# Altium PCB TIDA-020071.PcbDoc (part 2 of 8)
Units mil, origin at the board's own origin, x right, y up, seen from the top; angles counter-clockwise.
Board outline 5750 x 4050 mil, 6 copper layers (Top Layer, GND PLANE-1, SIGNAL LAYER, SIGNAL/POWER LAYER, GND PLANE-2, Bottom Layer), stack 59.616 mil thick; 776 components, 498 nets, 2205 pads, 871 vias.
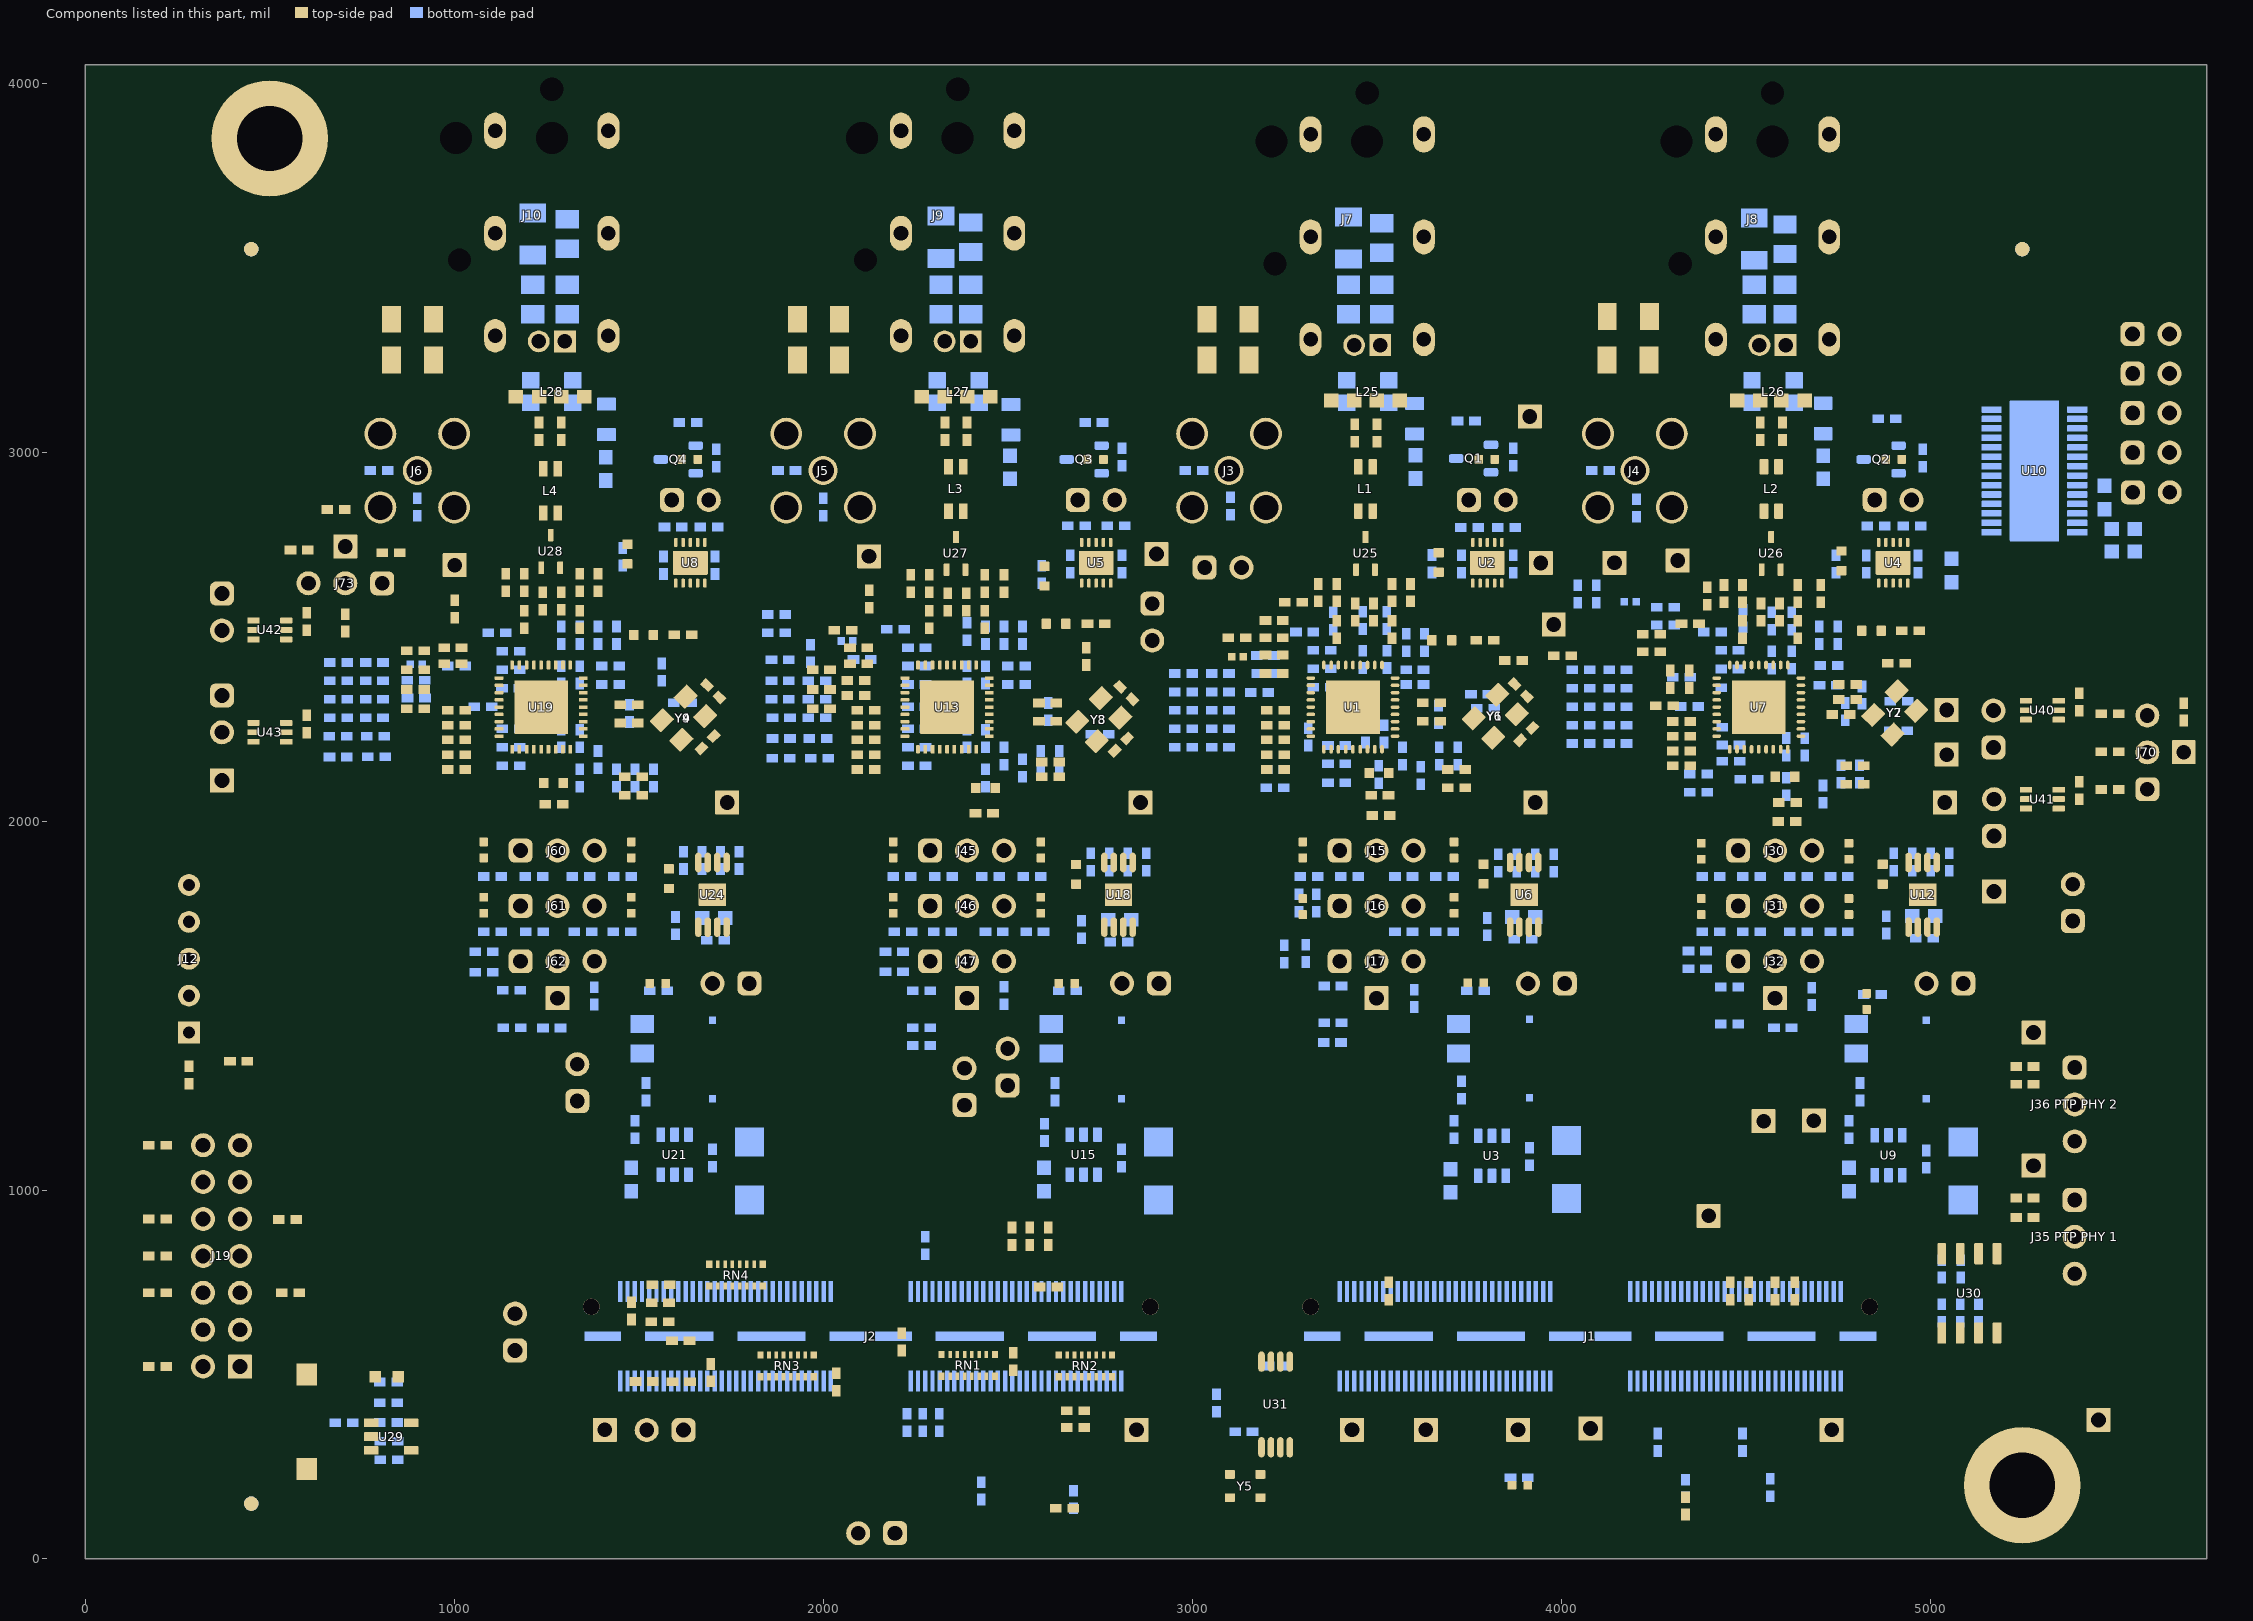
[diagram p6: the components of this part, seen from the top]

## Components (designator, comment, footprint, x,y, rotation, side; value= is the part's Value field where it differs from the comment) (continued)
R128 "CRCW04022K49FKED" 0402 2463.62,1700 r0 bottom value=2.49k
R129 "CRCW04022K20JNED" 0402 2192.68,1645.59 r0 bottom value=2.2k
R129-1 "CRCW040210K0FKED" 0402 2266.38,1540 r0 bottom value=10.0k
R129-2 "CRCW04022K20JNED" 0402 2490,1527.05 r270 bottom value=2.2k
R130 "ERJ-2GE0R00X" 0402 2750.8,2235.61 r0 bottom value=0
R131 "CRCW04022K20JNED" 0402 2733.62,3080 r0 bottom value=2.2k
R132 "CRCW04022K20JNED" 0402 2810,2986.38 r270 bottom value=2.2k
R133 "CRCW04022K20JNED" 0402 2662.11,1540 r0 bottom value=2.2k
R134 "ERJ-2GE0R00X" 0402 1562.35,2403.4 r270 bottom value=0
R135 "CRCW04022K49FKED" 0402 1886.38,2224 r180 bottom value=2.49k
R136 "CRCW04022K49FKED" 0402 1986.38,2224 r180 bottom value=2.49k
R137 "CRCW04022K49FKED" 0402 1886.38,2280 r180 bottom value=2.49k
R138 "CRCW04022K49FKED" 0402 1983.62,2280 r180 bottom value=2.49k
R139 "CRCW04022K49FKED" 0402 1883.62,2330 r180 bottom value=2.49k
R140 "CRCW04022K49FKED" 0402 1983.62,2330 r180 bottom value=2.49k
R141 "RC0402FR-074K7L" 0402 1883.62,2380 r180 bottom value=4.70k
R142 "CRCW04022K49FKED" 0402 1983.62,2380 r180 bottom value=2.49k
R143 "CRCW04022K49FKED" 0402 1883.6,2437.5 r180 bottom value=2.49k
R144 "CRCW04022K49FKED" 0402 1965.79,2454.41 r270 bottom value=2.49k
R145 "CRCW04020000Z0EDHP" 0402 2540,2503.62 r90 bottom value=0
R146 "CRCW04020000Z0EDHP" 0402 2196.38,2520 r180 bottom value=0
R147 "CRCW04020000Z0EDHP" 0402 2390,2513.62 r90 bottom value=0
R148 "CRCW04020000Z0EDHP" 0402 2253.62,2150 r0 bottom value=0
R149 "CRCW04020000Z0EDHP" 0402 2440,2116.38 r270 bottom value=0
R150 "CRCW04020000Z0EDHP" 0402 2700,1706.38 r270 bottom value=0
R151 "ERJ-2GE0R00X" 0402 1618.73,2320.66 r0 bottom value=0
R152 "CRCW04020000Z0EDHP" 0402 2266.38,1440 r0 bottom value=0
R153 "CRCW04020000Z0EDHP" 0402 2616.38,2160 r180 top value=0
R154 "CRCW04022K20JNED" 0402 2616.38,2120 r0 top value=2.2k
R155 "CRCW04022K20JNED" 0402 2640,2166.38 r270 bottom value=2.2k
R156 "CRCW04020000Z0EDHP" 0402 2590,2166.38 r270 bottom value=0
R157 "CRCW04020000Z0EDHP" 0402 2540,2143.62 r270 bottom value=0
R158 "CRCW04020000Z0EDHP" 0402 2116.38,2140 r180 top value=0
R159 "CRCW04020000Z0EDHP" 0402 2096.38,2470 r180 top value=0
R160 "CRCW04020000Z0EDHP" 0402 2116.38,2180 r180 top value=0
R161 "CRCW04020000Z0EDHP" 0402 2116.38,2220 r180 top value=0
R162 "CRCW04020000Z0EDHP" 0402 2116.38,2260 r180 top value=0
R163 "CRCW04020000Z0EDHP" 0402 2116.38,2300 r180 top value=0
R164 "ERJ-2GE0R00X" 0402 2000,2851.38 r90 bottom value=0
R165 "CRCW0402100RFKED" 0402 2608.46,2320.11 r180 top value=100
R166 "CRCW04021K00FKED" 0402 2608.46,2270.11 r180 top value=1.00k
R167 "CRCW04021K00FKED" 0402 1873.62,2560 r0 bottom value=1.00k
R168 "RMCF0805ZT0R00" FP-RMCF0805ZT0R00_0805-MFG 3603.12,3090.47 r270 bottom
R169 "CRCW040210K0FKED" 0402 2428.58,184.86 r90 bottom value=10.0k
R170 "CRCW040233K2FKED" 0402 1520,1266.38 r90 bottom value=33.2k
R171 "CRCW040210K0FKED" 0402 1490,1163.62 r270 bottom value=10.0k
R172 "CRCW04021K13FKED" 0402 1593.48,2796.89 r180 bottom value=1.13k
R173 "CRCW04024K53FKED" 0402 1690.73,2796.89 r180 bottom value=4.53k
R174 "CRCW04022K49FKED" 0402 1216.38,1850 r180 bottom value=2.49k
R175 "CRCW04022K20JNED" 0402 1103.62,1850 r0 bottom value=2.2k
R176 "CRCW04022K20JNED" 0402 1456.38,1850 r180 bottom value=2.2k
R177 "CRCW04022K49FKED" 0402 1343.62,1850 r0 bottom value=2.49k
R178 "CRCW04022K49FKED" 0402 1217.75,1700 r180 bottom value=2.49k
R179 "CRCW04022K20JNED" 0402 1103.62,1700 r0 bottom value=2.2k
R180 "CRCW04022K20JNED" 0402 1455,1700 r180 bottom value=2.2k
R181 "CRCW04022K49FKED" 0402 1349.21,1700 r0 bottom value=2.49k
R182 "CRCW04022K20JNED" 0402 1080.69,1645.59 r0 bottom value=2.2k
R182-1 "CRCW040210K0FKED" 0402 1155.24,1541.59 r0 bottom value=10.0k
R182-2 "CRCW04022K20JNED" 0402 1380,1526.38 r270 bottom value=2.2k
R183 "RMCF0805ZT0R00" FP-RMCF0805ZT0R00_0805-MFG 4710.44,3091.06 r270 bottom
R184 "CRCW04022K20JNED" 0402 1633.62,3080 r0 bottom value=2.2k
R185 "CRCW04022K20JNED" 0402 1710,2983.62 r270 bottom value=2.2k
R186 "CRCW04022K20JNED" 0402 1553.62,1540 r0 bottom value=2.2k
R187 "RMCF0805ZT0R00" FP-RMCF0805ZT0R00_0805-MFG 2508.66,3087.65 r270 bottom
R188 "CRCW04022K49FKED" 0402 685,2230 r180 bottom value=2.49k
R189 "CRCW04022K49FKED" 0402 786.38,2230 r180 bottom value=2.49k
R190 "CRCW04022K49FKED" 0402 686.38,2280 r180 bottom value=2.49k
R191 "CRCW04022K49FKED" 0402 783.62,2280 r180 bottom value=2.49k
R192 "CRCW04022K49FKED" 0402 686.38,2330 r180 bottom value=2.49k
R193 "CRCW04022K49FKED" 0402 783.62,2330 r180 bottom value=2.49k
R194 "CRCW04022K49FKED" 0402 686.38,2380 r180 bottom value=2.49k
R195 "CRCW04022K49FKED" 0402 783.62,2380 r180 bottom value=2.49k
R196 "RC0402FR-0710KL" 0402 686.38,2430 r180 bottom value=10.0k
R197 "CRCW04022K49FKED" 0402 783.62,2430 r180 bottom value=2.49k
R198 "CRCW04020000Z0EDHP" 0402 1440,2503.62 r90 bottom value=0
R199 "CRCW04020000Z0EDHP" 0402 1116.38,2510 r180 bottom value=0
R200 "CRCW04020000Z0EDHP" 0402 1340,2503.62 r90 bottom value=0
R201 "CRCW04020000Z0EDHP" 0402 1153.62,2150 r0 bottom value=0
R202 "CRCW04020000Z0EDHP" 0402 1340,2116.38 r270 bottom value=0
R203 "CRCW04020000Z0EDHP" 0402 1600,1716.38 r270 bottom value=0
R204 "RMCF0805ZT0R00" FP-RMCF0805ZT0R00_0805-MFG 1412.78,3088.69 r270 bottom
R205 "CRCW04020000Z0EDHP" 0402 1156.38,1440 r0 bottom value=0
R206 "CRCW04020000Z0EDHP" 0402 1486.38,2120 r180 top value=0
R207 "CRCW04022K20JNED" 0402 1486.38,2070 r0 top value=2.2k
R208 "CRCW04022K20JNED" 0402 1540,2116.38 r270 bottom value=2.2k
R209 "CRCW04020000Z0EDHP" 0402 1490,2116.38 r270 bottom value=0
R210 "CRCW04020000Z0EDHP" 0402 1440,2116.38 r90 bottom value=0
R211 "CRCW04020000Z0EDHP" 0402 1006.38,2140 r180 top value=0
R212 "CRCW04020000Z0EDHP" 0402 996.38,2470 r180 top value=0
R213 "CRCW04020000Z0EDHP" 0402 1006.38,2180 r180 top value=0
R214 "CRCW04020000Z0EDHP" 0402 1006.38,2220 r180 top value=0
R215 "CRCW04020000Z0EDHP" 0402 1006.38,2260 r180 top value=0
R216 "CRCW04020000Z0EDHP" 0402 1006.38,2300 r180 top value=0
R217 "ERJ-2GE0R00X" 0402 900,2851.38 r90 bottom value=0
R218 "CRCW0402100RFKED" 0402 1473.82,2315.55 r180 top value=100
R219 "CRCW04021K00FKED" 0402 1473.82,2265.55 r180 top value=1.00k
R220 "CRCW060310K0FKEA" 0603 5523.83,2730.7 r180 bottom value=10.0k
R221 "CRCW04020000Z0EDHP" 0402 3441.73,2566.14 r270 top value=0
R222 "CRCW04020000Z0EDHP" 0402 3491.73,2566.14 r270 top value=0
R223 "CRCW040226R7FKED" 0402 3391.73,2618.9 r270 top value=26.7
R224 "CRCW040226R7FKED" 0402 3541.73,2618.9 r90 top value=26.7
R225 "ERJ-P06F1001V" 0805_HV 3514.26,3413.28 r270 bottom value=1.00k
R226 "ERJ-P06F1001V" 0805_HV 3423.94,3413.28 r270 bottom value=1.00k
R227 "CRCW0805100KFKEA" 0805_HV 3514.26,3580.42 r270 bottom value=100k
R228 "CRCW12061M00JNEA" 1206 3097.09,3360 r180 top value=1.0Meg
R229 "CRCW060310K0FKEA" 0603 5523.83,2791.5 r180 bottom value=10.0k
R230 "CRCW06033K30JNEA" 0603 5472.83,2876.76 r90 bottom value=3.3k
R232 "CRCW04020000Z0EDHP" 0402 4541.73,2566.14 r270 top value=0
R233 "CRCW04020000Z0EDHP" 0402 4591.73,2566.14 r270 top value=0
R234 "CRCW040226R7FKED" 0402 4491.73,2616.14 r270 top value=26.7
R235 "CRCW040226R7FKED" 0402 4641.73,2616.14 r90 top value=26.7
R236 "ERJ-P06F1001V" 0805_HV 4607.16,3413.22 r270 bottom value=1.00k
R237 "ERJ-P06F1001V" 0805_HV 4523.48,3413.31 r270 bottom value=1.00k
R238 "CRCW0805100KFKEA" 0805_HV 4607.16,3576.85 r270 bottom value=100k
R239 "CRCW12061M00JNEA" 1206 4182.06,3367.29 r180 top value=1.0Meg
R243 "CRCW04020000Z0EDHP" 0402 2337.64,2593.62 r270 top value=0
R244 "CRCW04020000Z0EDHP" 0402 2387.64,2593.62 r270 top value=0
R245 "CRCW040226R7FKED" 0402 2287.64,2643.62 r270 top value=26.7
R246 "CRCW040226R7FKED" 0402 2437.64,2643.62 r90 top value=26.7
R247 "ERJ-P06F1001V" 0805_HV 2399.79,3413.28 r270 bottom value=1.00k
R248 "ERJ-P06F1001V" 0805_HV 2319.11,3413.28 r270 bottom value=1.00k
R249 "CRCW0805100KFKEA" 0805_HV 2399.79,3582.22 r270 bottom value=100k
R250 "CRCW12061M00JNEA" 1206 1987.09,3360 r180 top value=1.0Meg
R251 "CRCW04020000Z0EDHP" 0402 1240,2596.38 r270 top value=0
R252 "CRCW04020000Z0EDHP" 0402 1290,2596.38 r270 top value=0
R253 "CRCW040226R7FKED" 0402 1190,2646.38 r270 top value=26.7
R254 "CRCW040226R7FKED" 0402 1340,2646.38 r270 top value=26.7
R255 "ERJ-P06F1001V" 0805_HV 1306.77,3413.28 r270 bottom value=1.00k
R256 "ERJ-P06F1001V" 0805_HV 1212.98,3413.28 r270 bottom value=1.00k
R257 "CRCW0805100KFKEA" 0805_HV 1306.77,3590.99 r270 bottom value=100k
R258 "CRCW12061M00JNEA" 1206 887.09,3360 r180 top value=1.0Meg
R259 "ERA2AEB222X" 0402 823.62,269.09 r0 bottom value=2.20k
R260 "ERJ-2RKF1004X" 0402 822.24,369.76 r180 bottom value=1.00Meg
R261 "CRCW04020000Z0EDHP" 0402 701.38,369.09 r0 bottom value=0
R262 "RC0402FR-07470RL" 0402 822.24,423.09 r0 bottom value=470
R263 "CRCW04020000Z0EDHP" 0402 822.24,479.61 r180 bottom value=0
R264 "CRCW04022K20JNED" 0402 5031.5,666.38 r90 bottom value=2.2k
R265 "CRCW04022K20JNED" 0402 5081.5,666.38 r90 bottom value=2.2k
R266 "CRCW04022K20JNED" 0402 5131.5,666.38 r90 bottom value=2.2k
R267 "CRCW04022K20JNED" 0402 5083.11,786.38 r270 bottom value=2.2k
R268 "CRCW04022K20JNED" 0402 1480.68,672.56 r270 top value=2.2k
R269 "RG1005P-202-B-T5" 0402 3140,345 r180 bottom value=2.00k
R271 "ERJ-2GE0R00X" 0402 3668,2288.9 r270 bottom value=0
R272 "ERJ-2GE0R00X" 0402 4770,2296.38 r270 bottom value=0
R273 "ERJ-2GE0R00X" 0402 2609.84,2296.48 r270 bottom value=0
R274 "ERJ-2GE0R00X" 0402 1475.2,2291.93 r270 bottom value=0
R275 "CRCW040210K0FKED" 0402 3380,1400 r0 bottom value=10.0k
R276 "CRCW040210K0FKED" 0402 4600.79,1440 r180 bottom value=10.0k
R277 "CRCW040210K0FKED" 0402 2266.69,1391.61 r0 bottom value=10.0k
R278 "CRCW040210K0FKED" 0402 1264.38,1439 r180 bottom value=10.0k
R279 "ERJ-2RKF1002X" 0402 1995,2410 r0 top value=0
R280 "ERJ-2GE0R00X" 0402 2096.38,2426.06 r0 top value=0
R281 "ERJ-2RKF1002X" 0402 895,2356.65 r0 top value=0
R282 "ERJ-2GE0R00X" 0402 996.38,2426.06 r0 top value=0
R285 "CRCW04020000Z0EDHP" 0402 4633.27,726.38 r90 top value=0
R286 "CRCW04020000Z0EDHP" 0402 2610.95,737.2 r0 top value=0
R287 "CRCW04020000Z0EDHP" 0402 2610,874.68 r90 top value=0
R288 "CRCW04020000Z0EDHP" 0402 2560,874.68 r90 top value=0
R300 "CRCW04020000Z0EDHP" 0402 1614.1,591.7 r180 top value=0
R301 "CRCW04020000Z0EDHP" 0402 1558.62,694.49 r180 top value=0
R302 "CRCW04020000Z0EDHP" 0402 2315,370 r90 bottom value=0
R303 "CRCW04020000Z0EDHP" 0402 2270,370 r90 bottom value=0
R304 "CRCW04020000Z0EDHP" 0402 1695,505 r270 top value=0
R305 "CRCW04020000Z0EDHP" 0402 1615.35,480 r0 top value=0
R306 "CRCW04022K20JNED" 0402 2227.24,370 r270 bottom value=2.2k
R307 "CRCW040210K0FKED" 0402 5487.86,2085.38 r180 top value=10.0k
R308 "RG1005P-202-B-T5" 0402 5487.86,2290.63 r180 top value=2.00k
R309 "CRCW040210K0FKED" 0402 5687.51,2296.01 r270 top value=10.0k
R310 "CRCW040210K0FKED" 0402 828.62,2727.33 r0 top value=10.0k
R311 "RG1005P-202-B-T5" 0402 579.95,2734.65 r180 top value=2.00k
R312 "CRCW04022K20JNED" 0402 1515,481.28 r180 top value=2.2k
R313 "CRCW040210K0FKED" 0402 679.37,2844.17 r0 top value=10.0k
R314 "CRCW04020000Z0EDHP" 0402 3222.42,2497.01 r0 top value=0
R315 "CRCW04022K20JNED" 0402 3121.31,2497.01 r0 top value=2.2k
R317 "CRCW04020000Z0EDHP" 0402 4283.04,2531.62 r0 bottom value=0
R318 "CRCW04022K20JNED" 0402 4283.04,2579.57 r180 bottom value=2.2k
R320 "CRCW04020000Z0EDHP" 0402 2105.72,2437.97 r0 bottom value=0
R321 "CRCW04022K20JNED" 0402 2053.72,2517.44 r0 top value=2.2k
R322 "CRCW04020000Z0EDHP" 0402 1006.38,2420 r0 bottom value=0
R323 "CRCW04022K20JNED" 0402 895,2461.69 r0 top value=2.2k
R324 "RG1005P-202-B-T5" 0402 5487.86,2187.79 r0 top value=2.00k
R330 "ERJ-2GE0R00X" 0402 3512.23,2015 r180 top value=0
R331 "ERJ-2GE0R00X" 0402 4612.23,1998.96 r0 top value=0
R332 "ERJ-2GE0R00X" 0402 3871.31,2435.02 r0 top value=0
R333 "ERJ-2GE0R00X" 0402 3222.42,2543.72 r180 top value=0
R340 "ERJ-2GE0R00X" 0402 3183,2348.11 r180 bottom value=0
R341 "CRCW04022K49FKED" 0402 3225,2090 r180 bottom value=2.49k
R342 "CRCW04022K49FKED" 0402 3226.38,2140 r0 bottom value=2.49k
R343 "CRCW04022K49FKED" 0402 3198.39,2448.62 r180 bottom value=2.49k
R344 "CRCW04022K49FKED" 0402 3200,2400 r0 bottom value=2.49k
R345 "CRCW04022K49FKED" 0402 3222.42,2400 r180 top value=2.49k
R346 "CRCW04022K49FKED" 0402 3222.42,2449.88 r0 top value=2.49k
R347 "ERJ-2GE0R00X" 0402 3307.92,1641.52 r90 bottom value=0
R348 "ERJ-2GE0R00X" 0402 4326.38,2390 r180 bottom value=0
R350 "CRCW04020000Z0EDHP" 0402 5256.85,978.23 r0 top value=0
R351 "CRCW04020000Z0EDHP" 0402 5256.85,925.72 r180 top value=0
R352 "CRCW04020000Z0EDHP" 0402 5256.85,1334.66 r0 top value=0
R353 "CRCW04020000Z0EDHP" 0402 5256.85,1286.9 r180 top value=0
R354 "CRCW04020000Z0EDHP" 0402 2684.25,356.1 r180 top value=0
R355 "CRCW04020000Z0EDHP" 0402 2684.25,401.4 r180 top value=0
R356 "CRCW04020000Z0EDHP" 0402 2035.59,479.61 r270 top value=0
R361 "ERJ-2GE0R00X" 0402 3382.48,2542.52 r90 bottom value=0
R362 "CRCW04020000Z0EDHP" 0402 2276.77,850 r90 bottom value=0
R363 "CRCW04020000Z0EDHP" 0402 2213.11,588.67 r270 top value=0
R364 "CRCW04020000Z0EDHP" 0402 2511.62,874.68 r90 top value=0
R365 "ERJ-2GE0R00X" 0402 4493.11,2549.22 r90 bottom value=0
R367 "ERJ-2GE0R00X" 0402 4776.37,2370 r0 top value=0
R370 "CRCW04022K49FKED" 0402 4372.4,2078.42 r180 bottom value=2.49k
R371 "CRCW04022K49FKED" 0402 4372.4,2127.38 r0 bottom value=2.49k
R372 "RC0402FR-0710KL" 0402 4347.35,2384.35 r270 top value=10.0k
R373 "CRCW04022K49FKED" 0402 4295.58,2384.35 r90 top value=2.49k
R374 "CRCW04022K49FKED" 0402 4244.81,2505.94 r180 top value=2.49k
R375 "CRCW04022K49FKED" 0402 4244.81,2458.7 r0 top value=2.49k
R376 "ERJ-2GE0R00X" 0402 4368.98,1600 r180 bottom value=0
R378 "CRCW04022K49FKED" 0402 1886.14,2170.14 r180 bottom value=2.49k
R379 "CRCW04022K49FKED" 0402 1990,2170.14 r180 bottom value=2.49k
R380 "CRCW04022K49FKED" 0402 2088.9,2340.1 r180 top value=2.49k
R381 "CRCW04022K49FKED" 0402 2088.9,2380.9 r0 top value=2.49k
R382 "CRCW04022K49FKED" 0402 1995,2304.25 r180 top value=2.49k
R383 "CRCW04022K49FKED" 0402 1995,2356.65 r0 top value=2.49k
R384 "CRCW04020000Z0EDHP" 0402 2192.68,1591.7 r180 bottom value=0
R386 "CRCW04022K49FKED" 0402 685.65,2173.44 r180 bottom value=2.49k
R387 "CRCW04022K49FKED" 0402 789.07,2174.29 r180 bottom value=2.49k
R388 "CRCW04022K49FKED" 0402 897.24,2333.35 r180 bottom value=2.49k
R389 "CRCW04022K49FKED" 0402 896.57,2381.86 r0 bottom value=2.49k
R390 "RC0402FR-0710KL" 0402 895,2304.25 r180 top value=10.0k
R391 "CRCW04022K49FKED" 0402 895,2410 r0 top value=2.49k
R392 "CRCW04020000Z0EDHP" 0402 1080.69,1590 r180 bottom value=0
R400 "ERJ-2GE0R00X" 0402 195.53,821.45 r0 top value=0
R404 "ERJ-2GE0R00X" 0402 4003.71,2447.77 r180 top value=0
R408 "ERJ-2GE0R00X" 0402 4350,2534.62 r180 top value=0
R409 "ERJ-2GE0R00X" 0402 2125,2601.41 r90 top value=0
R410 "ERJ-2GE0R00X" 0402 281.23,1311.38 r90 top value=0
R411 "ERJ-2GE0R00X" 0402 548.03,920.35 r180 top value=0
R412 "ERJ-2GE0R00X" 0402 195.53,1121.45 r0 top value=0
R413 "ERJ-2GE0R00X" 0402 195.53,721.45 r0 top value=0
R414 "ERJ-2GE0R00X" 0402 1001.87,2575.03 r90 top value=0
R415 "ERJ-2GE0R00X" 0402 416.05,1348.93 r180 top value=0
R416 "ERJ-2GE0R00X" 0402 556.13,721.45 r180 top value=0
R417 "ERJ-2GE0R00X" 0402 195.53,921.45 r0 top value=0
R418 "ERJ-2GE0R00X" 0402 195.53,521.45 r0 top value=0
RN1 "EXB-2HVR000V" RESCAXS_EXB-2HV 2393.26,524.86 r0 top value=0
RN2 "EXB-2HVR000V" RESCAXS_EXB-2HV 2710.83,523.62 r0 top value=0
RN3 "EXB-2HVR000V" RESCAXS_EXB-2HV 1902.34,523.62 r0 top value=0
RN4 "EXB-2HVR000V" RESCAXS_EXB-2HV 1763.85,769.53 r180 top value=0
S1 "KSR221GLFS" KSR 600,372.05 r90 top
STRP1 "TSW-101-07-G-S" TSW-101-07-G-S 3980.09,2532.48 r90 top
STRP_1 "TSW-101-07-G-S" TSW-101-07-G-S 2903.53,2723.67 r90 top
STRP_1_2 "TSW-101-07-G-S" TSW-101-07-G-S 4316.08,2706.5 r90 top
U1 "DP83TG720SWRNDRQ1" RND0036A 3435.83,2308.74 r180 top
U2 "TPS74701QDRCRQ1" DRC0010A 3800,2700 r90 top
U3 "LMR14206XMKX/NOPB" DDC0006A_N 3812.6,1092.5 r90 bottom
U4 "TPS74701QDRCRQ1" DRC0010A 4900,2700 r90 top
U5 "TPS74701QDRCRQ1" DRC0010A 2740,2700 r90 top
U6 "TPS7B8233QDGNRQ1" DGN0008D_N 3900,1800 r90 top
U7 "DP83TG720SWRNDRQ1" RND0036A 4535.83,2308.74 r180 top
U8 "TPS74701QDRCRQ1" DRC0010A 1640,2700 r90 top
U9 "LMR14206XMKX/NOPB" DDC0006A_N 4887.4,1094.13 r90 bottom
U10 "TPS4H160BQPWPRQ1" PWP0028C_N 5282.83,2948.96 r180 bottom
U12 "TPS7B8233QDGNRQ1" DGN0008D_N 4980,1800 r90 top
U13 "DP83TC812R-Q1" RHA0036A-MFG 2335.83,2308.74 r180 top
U15 "LMR14206XMKX/NOPB" DDC0006A_N 2705.89,1095.87 r90 bottom
U18 "TPS7B8233QDGNRQ1" DGN0008D_N 2800.47,1800 r90 top
U19 "DP83TC812R-Q1" RHA0036A-MFG 1235.83,2308.74 r180 top
U21 "LMR14206XMKX/NOPB" DDC0006A_N 1597.4,1095.87 r90 bottom
U24 "TPS7B8233QDGNRQ1" DGN0008D_N 1700,1800 r90 top
U25 "TPD2E2U06QDCKRQ1" DCK0003A_N 3470,2725.71 r90 top
U26 "TPD2E2U06QDCKRQ1" DCK0003A_N 4569.3,2725.7 r90 top
U27 "TPD2E2U06QDCKRQ1" DCK0003A_N 2360,2725.71 r90 top
U28 "TPD2E2U06QDCKRQ1" DCK0003A_N 1261.51,2730.71 r90 top
U29 "TPS3838K33QDBVRQ1" DBV0005A_N 829.13,331.76 r0 top
U30 "CAT24C256WI-GT3" SOIC-8 5106.5,720.04 r90 top
U31 "LMK1C1104PW" PW0008A_N 3226.4,418.85 r90 top
U40 "TMUX1219DCKR" DCK0006A_N 5304.4,2300.42 r180 top
U41 "TMUX1219DCKR" DCK0006A_N 5304.4,2059.49 r180 top
U42 "TMUX1219DCKR" DCK0006A_N 500.45,2517.9 r180 top
U43 "TMUX1219DCKR" DCK0006A_N 500.45,2240.5 r180 top
Y1 "ABM8AIG-25.000MHZ-12-2Z-T3" Abracon_ABM8AIG 3821.72,2283.92 r135 top
Y2 "ABM8AIG-25.000MHZ-12-2Z-T3" Abracon_ABM8AIG 4903.91,2292.98 r135 top
Y3 "ABM8AIG-25.000MHZ-12-2Z-T3" Abracon_ABM8AIG 2747.24,2274.83 r135 top
Y4 "ABM8AIG-25.000MHZ-12-2Z-T3" Abracon_ABM8AIG 1621.51,2278.9 r135 top
Y5 "CDC6CE02500CDLE" DLE0004A-MFG 3143.55,197.8 r90 top
Y6 "CDC6CE02500CDLE" DLE0004A-MFG 3819.98,2283.39 r135 top
Y7 "CDC6CE02500CDLE" DLE0004A-MFG 4903.91,2292.98 r135 top
Y8 "CDC6CE02500CDLE" DLE0004A-MFG 2747.24,2274.83 r135 top
Y9 "CDC6CE02500CDLE" DLE0004A-MFG 1621.51,2278.9 r135 top
ZZ1 "This Assembly Note is for PCB labels only" AssemblyNoteLabel 340,5430 r0 top
ZZ2 "These assemblies are ESD sensitive, ESD precautions shall be observed." AssemblyNote 350,5310 r0 top
ZZ3 "These assemblies must be clean and free from flux and all contaminants. Use of no clean flux is not acceptable." AssemblyNote 340,5170 r0 top
ZZ4 "These assemblies must comply with workmanship standards IPC-A-610 Class 2, unless otherwise specified." AssemblyNote 330,5040 r0 top

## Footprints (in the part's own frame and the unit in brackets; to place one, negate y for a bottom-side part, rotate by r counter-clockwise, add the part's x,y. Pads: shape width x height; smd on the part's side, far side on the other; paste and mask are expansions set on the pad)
0402 [mm] "0402 from SM-752 data"
  rect 0.8x0.6 smd: 1(-0.6,0) 2(0.6,0)
  silkscreen extent -1.22,-0.52 1.22,0.52, body extent -0.55,-0.3 0.55,0.3, height 0.6
0603 [mm] "0603 from SM-752 data"
  rect 1x0.95 smd: 1(-0.8,0) 2(0.8,0)
  silkscreen extent -1.52,-0.69 1.52,0.69, body extent -0.87,-0.47 0.87,0.47, height 1
0805_HV [mil] "0805 with 30mil clearance between pads"
  rect 50x63 smd: 1(-40,0) 2(40,0)
  silkscreen extent -74,-40 74,40, body extent -43,-29 43,29, height 57
1206 [mm] "1206 from SM-752 data"
  rect 1.3x1.85 smd: 1(-1.45,0) 2(1.45,0)
  silkscreen extent -2.4,-1.21 2.4,1.21, body extent -1.7,-0.9 1.7,0.9, height 1.35
Abracon_ABM8AIG [mm] "SMD, 4-Leads, Body 3.2x2.5mm"
  rrect9% 1.1x1.3 smd: 1(-0.95,1.15) 2(-0.95,-1.15) 3(0.95,-1.15) 4(0.95,1.15)
  silkscreen extent -1.8,1.3 -1.28,2.07, body extent -1.3,-1.65 1.3,1.65, height 0.8
AMPHENOL_901-144-8RFX [mm] "SMA Straight Jack, TH"
  round 2 hole 1.5: 1(0,0)
  round 2.2 hole 1.7: 2(-2.54,2.54) 3(-2.54,-2.54) 4(2.54,-2.54) 5(2.54,2.54)
  silkscreen extent -3.7,-3.7 3.7,3.7, body extent -3.7,-3.7 3.7,3.7, height 9.93
AssemblyNote [mil] "Assembly Note"
AssemblyNoteLabel [mil] "Assembly Note for PCB Labels"
CE_Mark_5mm [mil] "Minimum text height for CE Mark"
  silkscreen extent -138,-98 138,98
DBV0005A_N [mm] "SOT23, 5-Leads, Body 2.9x1.6mm, Pitch 0.95mm, Lead Span 2.8mm, IPC Medium Density"
  rrect17% 1x0.6 smd: 1(-1.375,0.95) 2(-1.375,0) 3(-1.375,-0.95) 4(1.375,-0.95) 5(1.375,0.95)
  silkscreen extent -0.25,-1.55 0.25,1.55, body extent -1.42,-1.46 1.42,1.46, height 1.09
DCK0003A_N [mm] "SOT23, 3-Leads, Body 2.0x1.25mm, Pitch 0.65mm, Lead Span 2.1mm, IPC Medium Density"
  rrect25% 0.85x0.4 smd: 1(-1.125,0.65) 2(-1.125,-0.65) 3(1.125,0)
  silkscreen extent -1.02,-1.1 0.7,1.52, body extent -1.06,-1 1.06,1, height 1.1
DCK0006A_N [mm] "SOT23, 6-Leads, Body 2x1.3mm, Pitch 0.65mm, Lead Span 2.1mm, IPC Medium Density"
  rrect25% 0.85x0.4 smd: 1(-1.125,0.65) 2(-1.125,0) 3(-1.125,-0.65) 4(1.125,-0.65) 5(1.125,0) 6(1.125,0.65)
  silkscreen extent -1.5,-1.09 0.51,1.09, body extent -1.14,-1 1.14,1, height 0.95
DDC0006A_N [mm]
  rrect17% 1x0.6 smd: 1(-1.375,0.95) 2(-1.375,0) 3(-1.375,-0.95) 4(1.375,-0.95) 5(1.375,0) 6(1.375,0.95)
  silkscreen extent -1.75,-1.52 0.7,1.53, body extent -1.43,-1.48 1.43,1.49, height 0.92
DGN0008D_N [mm] "TSOP, 8-Leads, Body 3x3mm, Pitch 0.65mm, Thermal Pad 1.89x1.57mm, IPC Medium Density"
  rrect100% 1.35x0.45 smd: 1(-2.225,0.975) 2(-2.225,0.325) 3(-2.225,-0.325) 4(-2.225,-0.975) 5(2.225,-0.975) 6(2.225,-0.325) 7(2.225,0.325) 8(2.225,0.975)
  rrect6% 1.57x1.89 smd: 9(0,0)
  silkscreen extent -2.73,-1.55 0.95,1.55, body extent -2.46,-1.5 2.46,1.5, height 1.1
DLE0004A-MFG [mm]
  rrect17% 0.6x0.7 smd paste-1000 mask+0: 1(-0.8,1.05) 2(-0.8,-1.05) 3(0.8,-1.05) 4(0.8,1.05)
  silkscreen extent -1.9,-1.65 1.3,1.65, body extent -1.4,-1.75 1.4,1.75, height 0.25
DRC0010A [mm] "SON, 10-Leads, Body 3x3mm, Pitch 0.5mm, Thermal Pad 2.4x1.65mm, TI Recommended"
  rrect42% 0.6x0.24 smd: 1(-1.4,1) 2(-1.4,0.5) 3(-1.4,0) 4(-1.4,-0.5) 5(-1.4,-1) 6(1.4,-1) 7(1.4,-0.5) 8(1.4,0) 9(1.4,0.5) 10(1.4,1)
  rrect6% 1.65x2.4 smd paste-0.825: 11(0,0)
  silkscreen extent -1.7,-1.7 1.7,1.7, body extent -1.55,-1.55 1.55,1.55, height 1.01
FCC_disclaimer [mil]
Fiducial10-20 [mm]
  round 1 smd mask+0.5: 1(0,0)
  Top Layer keep-out circle w1.178: c0,0 r0.5
FP-ADL32VHR-3R9M_SMT_3MM2_2MM5-MFG [mm]
  rrect9% 1.2x1.15 smd paste+0 mask+0: 1(-1.45,0.775) 2(-1.45,-0.775) 3(1.45,-0.775) 4(1.45,0.775)
  silkscreen extent -2.75,-1.45 0.48,1.45, body extent -1.95,-1.25 1.95,1.25, height 2.5
FP-BLM18-0_15-t0_8-MFG [mm]
  rect 0.65x0.7 smd paste+0 mask+0: 1(-0.675,0) 2(0.675,0)
  silkscreen extent -0.87,-0.72 0.87,0.72, body extent -1.1,-0.58 1.1,0.58, height 0.25
FP-BLM18KG102SH1D_0603-MFG [mm]
  rrect15% 0.65x0.7 smd paste+0 mask+0: 1(-0.675,0) 2(0.675,0)
  silkscreen extent -0.88,-0.78 0.87,0.8, body extent -0.8,-0.4 0.8,0.4, height 0.95
"FP-BLM18KG601SH1_0603 (1608 Metric)-MFG" [mm]
  rrect15% 0.65x0.7 smd paste+0 mask+0: 1(-0.675,0) 2(0.675,0)
  silkscreen extent -0.87,-0.75 0.87,0.75, body extent -0.8,-0.4 0.8,0.4, height 0.95
FP-C0402-BB-MFG [mm]
  rect 0.52x0.52 smd paste+0 mask+0: 1(-0.4,0) 2(0.4,0)
  silkscreen extent -0.5,-0.64 0.5,0.64, body extent -0.5,-0.25 0.5,0.25, height 0.55
FP-DLW32MH101XT2_1210-MFG [mm]
  rrect17% 1.05x0.6 smd paste+0 mask+0: 1(-1.525,-0.5) 2(1.525,-0.5) 3(1.525,0.5) 4(-1.525,0.5)
  silkscreen extent -2.72,-1.35 1.7,1.35, body extent -2.15,-1.45 2.15,1.45, height 0.25
FP-DLW32MH201XK2_1210-MFG [mm]
  rect 1.05x0.6 smd paste+0 mask+0: 1(-1.525,-0.5) 2(1.525,-0.5) 3(1.525,0.5) 4(-1.525,0.5)
  body extent -2.15,-1.45 2.15,1.45, height 0.25
FP-RMCF0805ZT0R00_0805-MFG [mm]
  rrect11% 0.9x1.3 smd paste+0 mask+0: 1(-1.05,0) 2(1.05,0)
  silkscreen extent -0.23,-0.67 0.23,0.67, body extent -1,-0.63 1,0.63, height 0.65
Keystone_1902C [mil] "Hex Standoff, 4-40 threaded, nylon"
  round 1 on Mech4: 0(0,0)
  body extent -145,-126 146,126, height 501
KSR [mm] "C&K Components SPST switch"
  rect 1.5x1.4 smd: 1(-3.25,0) 2(3.25,0)
  silkscreen extent -3.2,-2 3.2,2, body extent -3,-1.9 3,1.9, height 2.65
Label_650x200 [mil] "Thermal Transfer Label"
  round 1 on Mech13: 0(0,0)
  silkscreen extent -325,-100 325,100, body extent -325,-100 325,100, height 1
Mill-Max_800-10-005-10-001000 [mm] "Mill-Max"
  rect 1.5x1.5 hole 0.85: 1(-5.08,0)
  round 1.5 hole 0.85: 2(-2.54,0) 3(0,0) 4(2.54,0) 5(5.08,0)
  silkscreen extent -6.35,-1.27 6.35,1.78, body extent -6.35,-1.27 6.35,1.27, height 8.13
"NY PMS 440 0025 PH"#1 [mm] "4-40 nylon screw and mounting hole"
  round 8 hole 4.5: 1(0,0)
  body extent -3.3,-3.3 3.3,3.3, height 2.69
"NY PMS 440 0025 PH"#2 [mm] "4-40 nylon screw and mounting hole"
  round 8 hole 4.5: 1(0,-0.081)
  body extent -3.3,-3.3 3.3,3.3, height 2.69
Pb-Free_Overlay_Small [mil]
  silkscreen extent -46,-46 46,46
PW0008A_N [mm] "TSOP, 8-Leads, Body 3x4.4mm, Pitch 0.65mm, IPC Medium Density"
  oval 1.4x0.45 smd: 1(-2.95,0.975) 2(-2.95,0.325) 3(-2.95,-0.325) 4(-2.95,-0.975) 5(2.95,-0.975) 6(2.95,-0.325) 7(2.95,0.325) 8(2.95,0.975)
  silkscreen extent -3.4,-1.55 1.85,1.55, body extent -3.21,-1.5 3.21,1.5, height 1.2
PWP0028C_N [mm] "TSOP, 28-Leads, Body 9.7x4.4mm, Pitch 0.65mm, Exposed Pad, IPC Medium Density"
  rrect22% 1.4x0.45 smd: 1(-2.95,4.225) 2(-2.95,3.575) 3(-2.95,2.925) 4(-2.95,2.275) 5(-2.95,1.625) 6(-2.95,0.975) 7(-2.95,0.325) 8(-2.95,-0.325) 9(-2.95,-0.975) 10(-2.95,-1.625) 11(-2.95,-2.275) 12(-2.95,-2.925) 13(-2.95,-3.575) 14(-2.95,-4.225) 15(2.95,-4.225) 16(2.95,-3.575) 17(2.95,-2.925) 18(2.95,-2.275) 19(2.95,-1.625) 20(2.95,-0.975) 21(2.95,-0.325) 22(2.95,0.325) 23(2.95,0.975) 24(2.95,1.625) 25(2.95,2.275) 26(2.95,2.925) 27(2.95,3.575) 28(2.95,4.225)
  rrect3% 3.1x5.18 on Bottom Paste: 29(0,0)
  rrect3% 3.4x9.7 smd paste-1.7 mask-1.7: 29(0,0)
  rrect3% 3.1x5.18 on Bottom Solder: 29(0,0)
  silkscreen extent -3.5,-4.9 2,4.9, body extent -3.2,-4.85 3.2,4.85, height 1.13
RESCAXS_EXB-2HV [mm] "Panasonic Resistor Array"
  rect 0.425x0.5 smd mask+0.07: 1(-1.837,-0.75) 8(1.837,-0.75) 9(1.837,0.75) 16(-1.837,0.75)
  rect 0.25x0.5 smd mask+0.07: 2(-1.25,-0.75) 3(-0.75,-0.75) 4(-0.25,-0.75) 5(0.25,-0.75) 6(0.75,-0.75) 7(1.25,-0.75) 10(1.25,0.75) 11(0.75,0.75) 12(0.25,0.75) 13(-0.25,0.75) 14(-0.75,0.75) 15(-1.25,0.75)
  silkscreen extent -2.05,-0.25 2.05,0.25, body extent -1.95,-0.8 1.95,0.8, height 0.55
RHA0036A-MFG [mm]
  rrect40% 0.6x0.25 smd paste+0 mask+0: 1(-2.9,2) 2(-2.9,1.5) 3(-2.9,1) 4(-2.9,0.5) 5(-2.9,0) 6(-2.9,-0.5) 7(-2.9,-1) 8(-2.9,-1.5) 9(-2.9,-2) 19(2.9,-2) 20(2.9,-1.5) 21(2.9,-1) 22(2.9,-0.5) 23(2.9,0) 24(2.9,0.5) 25(2.9,1) 26(2.9,1.5) 27(2.9,2)
  rrect40% 0.25x0.6 smd paste+0 mask+0: 10(-2,-2.9) 11(-1.5,-2.9) 12(-1,-2.9) 13(-0.5,-2.9) 14(0,-2.9) 15(0.5,-2.9) 16(1,-2.9) 17(1.5,-2.9) 18(2,-2.9) 28(2,2.9) 29(1.5,2.9) 30(1,2.9) 31(0.5,2.9) 32(0,2.9) 33(-0.5,2.9) 34(-1,2.9) 35(-1.5,2.9) 36(-2,2.9)
  rrect3% 3.7x3.7 smd paste-1000 mask+0: 37(0,0)
  silkscreen extent -4.13,-3.05 3.05,3.05, body extent -3.3,-3.3 3.3,3.3, height 0.25
RND0036A [mm] "TI"
  oval 0.6x0.25 smd: 1(-2.9,2) 2(-2.9,1.5) 3(-2.9,1) 4(-2.9,0.5) 5(-2.9,0) 6(-2.9,-0.5) 7(-2.9,-1) 8(-2.9,-1.5) 9(-2.9,-2) 19(2.9,-2) 20(2.9,-1.5) 21(2.9,-1) 22(2.9,-0.5) 23(2.9,0) 24(2.9,0.5) 25(2.9,1) 26(2.9,1.5) 27(2.9,2)
  oval 0.25x0.6 smd: 10(-2,-2.9) 11(-1.5,-2.9) 12(-1,-2.9) 13(-0.5,-2.9) 14(0,-2.9) 15(0.5,-2.9) 16(1,-2.9) 17(1.5,-2.9) 18(2,-2.9) 28(2,2.9) 29(1.5,2.9) 30(1,2.9) 31(0.5,2.9) 32(0,2.9) 33(-0.5,2.9) 34(-1,2.9) 35(-1.5,2.9) 36(-2,2.9)
  rect 3.7x3.7 smd paste-1.85: 37(0,0)
  silkscreen extent -3.17,-3.18 3.18,3.2, body extent -3,-3 3,3, height 0.81
SAMTEC_QTH-060-01-L-D-A [mm] "SMD, 60x2 Position, Body 40.01x5.97mm"
  rect 0.305x1.45 smd: 1(-17.25,3.086) 2(-17.25,-3.086) 3(-16.75,3.086) 4(-16.75,-3.086) 5(-16.25,3.086) 6(-16.25,-3.086) 7(-15.75,3.086) 8(-15.75,-3.086) 9(-15.25,3.086) 10(-15.25,-3.086) 11(-14.75,3.086) 12(-14.75,-3.086) 13(-14.25,3.086) 14(-14.25,-3.086) 15(-13.75,3.086) 16(-13.75,-3.086) 17(-13.25,3.086) 18(-13.25,-3.086) 19(-12.75,3.086) 20(-12.75,-3.086) 21(-12.25,3.086) 22(-12.25,-3.086) 23(-11.75,3.086) 24(-11.75,-3.086) 25(-11.25,3.086) 26(-11.25,-3.086) 27(-10.75,3.086) 28(-10.75,-3.086) 29(-10.25,3.086) 30(-10.25,-3.086) 31(-9.75,3.086) 32(-9.75,-3.086) 33(-9.25,3.086) 34(-9.25,-3.086) 35(-8.75,3.086) 36(-8.75,-3.086) 37(-8.25,3.086) 38(-8.25,-3.086) 39(-7.75,3.086) 40(-7.75,-3.086) 41(-7.25,3.086) 42(-7.25,-3.086) 43(-6.75,3.086) 44(-6.75,-3.086) 45(-6.25,3.086) 46(-6.25,-3.086) 47(-5.75,3.086) 48(-5.75,-3.086) 49(-5.25,3.086) 50(-5.25,-3.086) 51(-4.75,3.086) 52(-4.75,-3.086) 53(-4.25,3.086) 54(-4.25,-3.086) 55(-3.75,3.086) 56(-3.75,-3.086) 57(-3.25,3.086) 58(-3.25,-3.086) 59(-2.75,3.086) 60(-2.75,-3.086) 61(2.75,3.086) 62(2.75,-3.086) 63(3.25,3.086) 64(3.25,-3.086) 65(3.75,3.086) 66(3.75,-3.086) 67(4.25,3.086) 68(4.25,-3.086) 69(4.75,3.086) 70(4.75,-3.086) 71(5.25,3.086) 72(5.25,-3.086) 73(5.75,3.086) 74(5.75,-3.086) 75(6.25,3.086) 76(6.25,-3.086) 77(6.75,3.086) 78(6.75,-3.086) 79(7.25,3.086) 80(7.25,-3.086) 81(7.75,3.086) 82(7.75,-3.086) 83(8.25,3.086) 84(8.25,-3.086) 85(8.75,3.086) 86(8.75,-3.086) 87(9.25,3.086) 88(9.25,-3.086) 89(9.75,3.086) 90(9.75,-3.086) 91(10.25,3.086) 92(10.25,-3.086) 93(10.75,3.086) 94(10.75,-3.086) 95(11.25,3.086) 96(11.25,-3.086) 97(11.75,3.086) 98(11.75,-3.086) 99(12.25,3.086) 100(12.25,-3.086) 101(12.75,3.086) 102(12.75,-3.086) 103(13.25,3.086) 104(13.25,-3.086) 105(13.75,3.086) 106(13.75,-3.086) 107(14.25,3.086) 108(14.25,-3.086) 109(14.75,3.086) 110(14.75,-3.086) 111(15.25,3.086) 112(15.25,-3.086) 113(15.75,3.086) 114(15.75,-3.086) 115(16.25,3.086) 116(16.25,-3.086) 117(16.75,3.086) 118(16.75,-3.086) 119(17.25,3.086) 120(17.25,-3.086)
  rect 2.54x0.64 smd: A1(-18.44,0) A4(-1.55,0) A5(1.56,0) A8(18.45,0)
  rect 4.7x0.64 smd: A2(-13.17,0) A3(-6.82,0) A6(6.83,0) A7(13.18,0)
  round 1.15 hole 1.15 unplated mask+0: MH1(-19.24,2.03) MH2(19.24,2.03)
  silkscreen extent -20,-2.99 20,2.99, body extent -20.07,-3.56 19.94,3.56, height 4.32
SMA [mm] "Molded Diode, 2-Leads, Body 4.3x2.6mm, IPC Medium Density, based on OnSemi component dimensions and land pattern"
  rect 2x2 smd: 1(-2,0) 2(2,0)
  silkscreen extent -3.66,-1.57 2.79,1.57, body extent -2.6,-1.3 2.6,1.3, height 2.42
SOIC-8 [mm] "duplicate of SO-8.  SOIC, 8-Leads, Body 5.0x4.0mm (max), Pitch 1.27mm, IPC Medium Density"
  rrect17% 1.45x0.6 smd: 1(-2.725,1.905) 2(-2.725,0.635) 3(-2.725,-0.635) 4(-2.725,-1.905) 5(2.725,-1.905) 6(2.725,-0.635) 7(2.725,0.635) 8(2.725,1.905)
  silkscreen extent -3.5,-2.5 0.9,2.5, body extent -3,-2.45 3,2.45, height 1.63
SOT-23 [mm] "SOT23, 3-Leads, Body 2.9x1.3mm, Pitch 0.95mm, Lead Span 2.5mm, IPC Medium Density"
  rrect50% 1x0.6 smd: 1(-1.2,0.95) 2(-1.2,-0.95) 3(1.2,0)
  silkscreen extent -1.62,-1.5 0.7,1.5, body extent -1.16,-1.45 1.21,1.45, height 1
TE_1PORT_B1-B#1 [mm] "Header, 1.8mm, 2x1, TH"
  rect 1.5x1.5 hole 1: 1(-0.9,17.35)
  round 1.5 hole 1: 2(0.9,17.35)
  round 0 hole 2.2 unplated: MH1(0,3.35) MH2(6.6,3.35)
  round 0 hole 1.6 unplated: MH3(6.35,11.75) MH4(0,0)
  oval 1.5x2.3 hole 1 slot 1.775 at 90 deg: S1(-3.9,16.963) S4(3.9,16.963)
  oval 1.5x2.4 hole 1 slot 1.89 at 90 deg: S2(-3.9,9.905) S5(3.9,9.905)
  oval 1.5x2.5 hole 1 slot 2 at 90 deg: S3(-3.9,2.85) S6(3.9,2.85)
  silkscreen extent -7.45,-1.8 10.3,20, body extent -7.45,-1.8 10.3,19.3, height 13.5
TE_1PORT_B1-B#2 [mm] "Header, 1.8mm, 2x1, TH"
  rect 1.5x1.5 hole 1: 1(-0.9,17.35)
  round 1.5 hole 1: 2(0.9,17.35)
  round 0 hole 2.2 unplated mask+0: MH1(0,3.35) MH2(6.6,3.35)
  round 0 hole 1.6 unplated mask+0: MH3(6.35,11.75) MH4(0,0)
  oval 1.5x2.3 hole 1 slot 1.775 at 90 deg: S1(-3.9,16.963) S4(3.9,16.963)
  oval 1.5x2.4 hole 1 slot 1.89 at 90 deg: S2(-3.9,9.905) S5(3.9,9.905)
  oval 1.5x2.5 hole 1 slot 2 at 90 deg: S3(-3.9,2.85) S6(3.9,2.85)
  silkscreen extent -7.45,-1.8 10.3,20, body extent -7.45,-1.8 10.3,19.3, height 13.5
TI_Stacked_Overlay_Small [mil]
  silkscreen extent -418,-98 418,98
TSW-101-07-G-S [mm] "Samtec 100mil, 1pos, 230 mil above insulator"
  rrect6% 1.65x1.65 hole 1.016: 1(0,0)
  silkscreen extent -1.27,-1.27 1.27,1.27, body extent -1.27,-1.27 1.27,1.27, height 8.38
TSW-102-07-G-S [mm] "Samtec 100mil, 1x2, 230 mil above insulator"
  rrect50% 1.65x1.65 hole 1.016: 1(-1.27,0)
  round 1.65 hole 1.016: 2(1.27,0)
  silkscreen extent -3.17,-1.27 2.54,1.27, body extent -2.54,-1.27 2.54,1.27, height 8.38
TSW-103-07-G-S [mm] "Samtec 100mil, 1x3, 230 mil above insulator"
  rrect50% 1.65x1.65 hole 1.016: 1(-2.54,0)
  round 1.65 hole 1.016: 2(0,0) 3(2.54,0)
  body extent -3.81,-1.27 3.81,1.27, height 8.38
TSW-107-07-G-D [mm] "Samtec 100mil, 2x7, 230 mil above insulator"
  rrect6% 1.65x1.65 hole 1.016: 1(-7.62,-1.27)
  round 1.65 hole 1.016: 2(-7.62,1.27) 3(-5.08,-1.27) 4(-5.08,1.27) 5(-2.54,-1.27) 6(-2.54,1.27) 7(0,-1.27) 8(0,1.27) 9(2.54,-1.27) 10(2.54,1.27) 11(5.08,-1.27) 12(5.08,1.27) 13(7.62,-1.27) 14(7.62,1.27)
  silkscreen extent -9.91,-2.54 8.89,2.54, body extent -8.89,-2.54 8.89,2.54, height 8.38
WE-TPC-LH [mm] "Wurth Elektronik recommended land pattern, 2009-01-15"
  rect 0.5x0.5 smd: 1(-2.7,0) 2(2.7,0)
  Top Layer region: 0.95,3.15 0.95,3.15 0.95,1.987 1.228,1.838 1.563,1.563 1.838,1.228 2.042,0.846 2.168,0.431 2.211,0 2.168,-0.431 2.042,-0.846 1.838,-1.228 1.563,-1.563 1.228,-1.838 0.95,-1.987 0.95,-3.15 3.15,-3.15 3.15,-3.15 3.15,3.15 0.95,3.15
  Top Layer region: -0.95,3.15 -0.95,3.15 -0.95,1.987 -1.228,1.838 -1.563,1.563 -1.838,1.228 -2.042,0.846 -2.168,0.431 -2.211,0 -2.168,-0.431 -2.042,-0.846 -1.838,-1.228 -1.563,-1.563 -1.228,-1.838 -0.95,-1.987 -0.95,-3.15 -3.15,-3.15 -3.15,-3.15 -3.15,3.15 -0.95,3.15
  silkscreen extent -3.4,-3.4 3.4,3.4, body extent -3.05,-3.05 3.05,3.05, height 3
WEEE_Minimum [mil] "WEEElie bin"
  silkscreen extent -95,-172 99,104
WL-SMCC_0402_Green [mm] "SMD, 2-Leads, Body 1x0.5mm"
  rrect17% 0.6x0.6 smd: 1(-0.55,0) 2(0.55,0)
  body extent -0.5,-0.25 0.5,0.25, height 0.39
WL-SMCW_RED [mm] "WURTH"
  rect 0.8x0.8 smd: 1(-0.8,0) 2(0.8,0)
  silkscreen extent -1.9,-0.8 1.2,0.8, body extent -0.85,-0.45 0.85,0.45, height 0.8

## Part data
1V8 3V3 3V3IO 5V0 12V0 CLKOUT/GPIO GND GND GND GND GND GND INH-1 INH-2 INH-3 INH-4 INT-1 INT-2 INT-3 INT-4 J11 J18 J24 "J35_1 PTP PHY 1" "J63_1 PTP PHY 2" J70_1 J73_1 LED_0_2 LED_1_2 MCASP0_AXR5 MCASP1_AXR5 MCASP1_AXR6 STRP1 STRP_1 STRP_1_2: library part CMP-0075403-1, "Header, 100mil, 1pos, Gold, TH", Color=Black, Current_A=6.3A, Manufacturer=Samtec, Supplier Part Number 1=SAM1029-01-ND, Voltage_V=550V
C1 C15 C16 C17 C18 C19 C25 C28 C35 C49 C50 C51 C52 C53 C59 C62 C68 C69 C83 C84 C87 C93 C96 C117 C118 C121 C127 C130 C175 C177 C178 C200 C201 C202 C203: library part CMP-0006279-2, "CAP, CERM, 0.1 uF, 50 V, +/- 10%, X5R, 0402", Cap_Case=0402, Manufacturer=TDK, Supplier Part Number 1=445-5942-1-ND, TempCo=X5R, Tolerance_%=10%, Value1="0.039064 ohm", Value2=50V, ValueDisplayed=100nF
C2 C36 C70 C104: library part CMP-0007020-5, "CAP, CERM, 2.2 uF, 35 V, +/- 10%, X5R, 0603", Cap_Case=0603, Manufacturer=TDK, Supplier Part Number 1=445-8025-1-ND, TempCo=X5R, Tolerance_%=10%, Value1="0.007674 ohm", Value2=35V, ValueDisplayed=2.2uF
C3 C37 C71 C105: library part CMP-0006567-2, "CAP, CERM, 0.15 uF, 10 V, +/- 10%, X5R, 0402", Cap_Case=0402, Manufacturer=MuRata, Supplier Part Number 1=GRM155R61A154KE19-ND, TempCo=X5R, Tolerance_%=10%, Value1=Unknown, Value2=10V, ValueDisplayed=0.15uF
C4 C38 C72 C106: library part CMP-0007825-2, "CAP, CERM, 47 uF, 10 V, +/- 20%, X5R, 0805", Cap_Case=0805, Manufacturer=TDK, Supplier Part Number 1=445-8239-1-ND, TempCo=X5R, Tolerance_%=20%, Value1="0.00294 ohm", Value2=10V, ValueDisplayed=47uF
C5 C6 C39 C40 C73 C74 C107 C108: library part CMP-0006608-2, "CAP, CERM, 1 uF, 25 V, +/- 10%, X5R, 0402", Cap_Case=0402, Manufacturer=MuRata, Supplier Part Number 1=490-10017-1-ND, TempCo=X5R, Tolerance_%=10%, Value1=Unknown, Value2=25V, ValueDisplayed=1uF
C7 C8 C9 C27 C41 C42 C43 C61 C75 C76 C77 C95 C109 C110 C111 C129: library part CMP-0006564-2, "CAP, CERM, 10 uF, 10 V, +/- 20%, X5R, 0402", Cap_Case=0402, Manufacturer=MuRata, TempCo=X5R, Tolerance_%=20%, Value1=Unknown, Value2=10V, ValueDisplayed=10uF
C10 C11 C12 C13 C14 C44 C45 C46 C47 C48 C78 C79 C80 C81 C82 C112 C113 C114 C115 C116: library part CMP-0006278-2, "CAP, CERM, 2.2 uF, 25 V, +/- 10%, X5R, 0402", Cap_Case=0402, Manufacturer=TDK, Supplier Part Number 1=445-9090-1-ND, TempCo=X5R, Tolerance_%=10%, Value1=Unknown, Value2=25V, ValueDisplayed=2.2uF
C20 C21 C22 C23 C24 C29 C30 C54 C55 C56 C57 C58 C63 C64 C88 C89 C90 C91 C92 C97 C98 C122 C123 C124 C125 C126 C131 C132: library part CMP-0006236-2, "CAP, CERM, 0.01 uF, 50 V, +/- 5%, X7R, 0402", Cap_Case=0402, Manufacturer=Kemet, Supplier Part Number 1=399-7758-1-ND, TempCo=X7R, Tolerance_%=5%, Value1=Unknown, Value2=50V, ValueDisplayed=10nF
C26 C60 C94 C128: library part CMP-0007007-5, "CAP, CERM, 10 uF, 25 V, +/- 20%, X5R, 0603", Cap_Case=0603, Manufacturer=TDK, Supplier Part Number 1=445-9015-1-ND, TempCo=X5R, Tolerance_%=20%, Value1="0.004639 ohm", Value2=25V, ValueDisplayed=10uF
C31 C34 C65 C99 C102 C133 C137 C138 C148 C149 C159 C160 C167 C168: library part CMP-0006438-2, "CAP, CERM, 22 pF, 50 V, +/- 1%, C0G/NP0, 0402", Cap_Case=0402, Manufacturer=MuRata, Supplier Part Number 1=490-8589-1-ND, TempCo=C0G/NP0, Tolerance_%=1%, Value1=Unknown, Value2=50V, ValueDisplayed=22pF
C32 C33 C66 C67 C100 C101 C134 C135: library part CMP-0750098-1, "CAP, CERM, 27 pF, 50 V,+/- 5%, C0G/NP0, 0402", Cap_Case=0402, Manufacturer=Kemet, TempCo=C0G/NP0, Tolerance_%=5%, Value2=50V, ValueDisplayed=27pF
C85 C86 C119 C120: library part CMP-0006580-2, "CAP, CERM, 0.47 uF, 10 V, +/- 10%, X5R, 0402", Cap_Case=0402, Manufacturer=MuRata, Supplier Part Number 1=490-3264-1-ND, TempCo=X5R, Tolerance_%=10%, Value1=Unknown, Value2=10V, ValueDisplayed=0.47uF
C103: library part CMP-0084679-1, "CAP, CERM, 0.1 µF, 25 V,+/- 10%, X7R, AEC-Q200 Grade 1, 0603", Cap_Case=0603, Manufacturer=MuRata, TempCo=X7R, Tolerance_%=10%, Value2=25V, ValueDisplayed=0.1µF
C136 C145 C146 C147: library part CMP-0082523-1, "CAP, CERM, 1 µF, 25 V,+/- 10%, X7R, AEC-Q200 Grade 1, 0603", Cap_Case=0603, Manufacturer=TDK, Supplier Part Number 1=445-9819-1-ND, TempCo=X7R, Tolerance_%=10%, Value2=25V, ValueDisplayed=1µF
C139 C140 C150 C151 C161 C162 C169 C170: library part CMP-0006467-2, "CAP, CERM, 47 pF, 50 V, +/- 1%, C0G/NP0, 0402", Cap_Case=0402, Manufacturer=MuRata, Supplier Part Number 1=490-6241-1-ND, TempCo=C0G/NP0, Tolerance_%=1%, Value1=Unknown, Value2=50V, ValueDisplayed=47pF
C141 C142 C152 C153 C163 C164 C171 C172: library part CMP-0006356-2, "CAP, CERM, 0.1 uF, 50 V, +/- 10%, X7R, AEC-Q200 Grade 1, 0402", Cap_Case=0402, Manufacturer=MuRata, Supplier Part Number 1=490-10672-1-ND, TempCo=X7R, Tolerance_%=10%, Value1=Unknown, Value2=50V, ValueDisplayed=0.1uF
C143 C144 C154 C155 C165 C166 C173 C174: library part CMP-0008920-2, "CAP, CERM, 4700 pF, 1000 V, +/- 10%, X7R, 1206", Cap_Case=1206, Manufacturer=MuRata, Supplier Part Number 1=490-3498-1-ND, TempCo=X7R, Tolerance_%=10%, Value1=Unknown, Value2=1000V, ValueDisplayed=4n7
C176: library part CMP-0006608-2, "CAP, CERM, 1 uF, 25 V, +/- 10%, X5R, 0402", Cap_Case=0402, Manufacturer=MuRata, Supplier Part Number 1=490-10017-1-ND, TempCo=X5R, Tolerance_%=10%, Value1=Unknown, Value2=25V, ValueDisplayed=100nF
C314 C317 C320 C322: library part CMP-2008-02147-2, "Cap Ceramic 0.047uF 10V X7R 10% SMD 0402 125°C Paper T/R", Capacitance="47,000 pF", Manufacturer=Kemet, Package=C0402-BB, Temperature="-55°C to +125°C", Temperature Characteristic=X7R, Temperature Coefficient=15%, Temperature Range High=+125°C, Temperature Range Low=-55°C, Tolerance=0.1, Voltage Rating="10 V"
D1 D9 D17 D25: library part CMP-0028389-2, "Diode, Schottky, 60 V, 1 A, SMA", Manufacturer="Diodes Inc.", Value1=1A, Value2=0.7V
D2 D3 D4 D5 D6 D7 D8 D11 D12 D13 D14 D15 D16 D19 D20 D21 D22 D23 D24 D27 D28 D29 D30 D31 D32: library part CMP-0081765-2, "LED, Green, SMD", Color=Green, Manufacturer="Wurth Elektronik", Power_TotalModule=99mW, Value1=0.099W, Value2=3.2V
D33 D34 D35 D36 D37 D38 D39 D40: library part CMP-0086344-1, "Diode, TVS, Bi, AEC-Q101, 0603", Manufacturer=Panasonic
D41: library part CMP-0002947-3, "LED, Red, SMD", Color=Red, Manufacturer="Wurth Elektronik", Power_TotalModule=72mW, Value1=0.072W, Value2=2V
FID1 FID2 FID3 FID4 FID5 FID6: library part CMP-0077181-1, "Fiducial mark.  There is nothing to buy or mount.", Manufacturer=N/A
H1 H3: library part CMP-0003617-1, "Machine Screw, Round, #4-40 x 1/4, Nylon, Philips panhead", Manufacturer="B&F Fastener Supply", Supplier Part Number 1=H542-ND
H5 H7: library part CMP-0003610-1, "Standoff, Hex, 0.5\"L #4-40 Nylon", Manufacturer=Keystone, Supplier Part Number 1=36-1902C-ND
J1 J2: library part CMP-0056023-2, "Socket, 0.5MM, 60x2, Gold, SMT", Manufacturer=Samtec, Supplier Part Number 1=SAM8189-ND
J3 J4 J5 J6: library part CMP-0055833-1, "SMA Straight Jack, Gold, 50 Ohm, TH", Manufacturer="Amphenol RF", Supplier Part Number 1=ARFX1231-ND
J7 J8 J9 J10: library part CMP-0054903-1, "Header(shrouded), 2x1, R/A, TH", Manufacturer="TE Connectivity"
J12: library part CMP-0055088-1, "Header, 100mil, 5x1, TH", Manufacturer=Mill-Max, Supplier Part Number 1=ED7205-ND
J13 J14 J20 J21 J22 J23 J25 J26 J27 J28 J29 J33 J34 J37 J43 J44 J58 J59 J71 J72 J74 J75 MCASP0_ACLKX MCASP0_AFSX MCASP1_ACLKX MCASP1_AFSX: library part CMP-0075405-3, "Header, 100mil, 2x1, Gold, TH", Color=Black, Current_A=6.3A, Manufacturer=Samtec, Supplier Part Number 1=SAM1029-02-ND, Voltage_V=550V
J15 J16 J17 J30 J31 J32 "J35 PTP PHY 1" "J36 PTP PHY 2" J45 J46 J47 J60 J61 J62 J70 J73: library part CMP-0075407-2, "Header, 100mil, 3x1, Gold, TH", Color=Black, Current_A=6.3A, Manufacturer=Samtec, Supplier Part Number 1=SAM1029-03-ND, Voltage_V=550V
J19: library part CMP-0081507-1, "Header, 2.54mm, 7x2, Gold with Tin tail, TH", Color=Black, Manufacturer=Samtec, Supplier Part Number 1=TSW-107-07-L-D-006-ND
L1 L2: library part CMP-0090833-1, "100μH @ 100kHz 2 Line Common Mode Choke Surface Mount 100mA DCR 3.12Ω", Manufacturer=Murata, Mouser Part Number=81-DLW32MH101XT2L, Operating Temperature Range="-40°C to +125°C", Test Frequency=100kHz, Tolerance_%=-25/+50%
L3 L4: library part CMP-0087001-1, "200µH @ 100kHz 2 Line Common Mode Choke Surface Mount 70mA DCR 4.8 Ohm", Manufacturer=Murata
L5 L6 L7 L8: library part CMP-0064420-2, "Inductor, Shielded Drum Core, Ferrite, 15 uH, 1.15 A, 0.07 ohm, SMD", Manufacturer="Wurth Elektronik", Supplier Part Number 1=732-1045-1-ND, Value1="0.07 ohm", Value2=1.15A, ValueDisplayed=15uH
L9 L12 L15 L20: library part CMP-0686-00363-3, "Chip Ferrite Bead, 0603, 1000Ω @ 100MHz, 0.35Ω, 25%, 600mA", Case Code (Imperial)=0603, Case Code (Metric)=1608, Current Rating=600mA, DC Resistance (DCR)=350mR, Max Operating Temperature=125°C, Min Operating Temperature=-55°C, Package Quantity=1, Test Frequency=100MHz, Tolerance=25%
L10 L11 L13 L14 L16 L17 L18 L19: library part CMP-0089848-1, "600 Ohms @ 100MHz 1 Power Line Ferrite Bead 0603 (1608 Metric) 1.3A 150mOhm", Digikey Part Number=490-13259-1-ND, Impedance At Frequency="600Ω @ 100MHz", Manufacturer=Murata, Mouser Part Number=81-BLM18KG601SH1D, Operating Temperature Range="-55°C to +125°C", Test Frequency=100MHz, Tolerance_%=25%
L21 L22 L23 L24: library part CMP-0089381-1, "1 kOhms @ 100MHz 1 Power Line Ferrite Bead 0603 (1608 Metric) 1A 200mOhm", Digikey Part Number=490-17348-1-ND, Impedance At Frequency="1kΩ @ 100MHz", Manufacturer=Murata, Mouser Part Number=81-BLM18KG102SH1D, Operating Temperature Range="-55°C to +125°C", Test Frequency=100MHz, Tolerance_%=25%
L25 L26 L27 L28: library part CMP-0098175-1, "Differential Mode Choke 3.9uH 540mA 0.36Ohm 3.2x2.5x2.5mm SMT", Manufacturer=TDK, Operating Temperature Range="-40°C to +150°C", Test Frequency=100kHz, Tolerance_%=20%
LBL1: library part CMP-0003625-1, "Thermal Transfer Printable Labels, 0.650\" W x 0.200\" H - 10,000 per roll", Manufacturer=Brady, Supplier Part Number 1=97C5133
Logo1: library part CMP-0074838-1, "Texas Instrument Corporate Signature"
Logo2: library part CMP-0074844-1
Logo3: library part CMP-0074847-1, "FCC_disclaimer"
Logo4: library part CMP-0074769-1
Logo5: library part CMP-0074839-1
Q1 Q2 Q3 Q4: library part CMP-0000376-2, "Transistor, NPN, 45 V, 0.1 A, SOT-23", Manufacturer="ON Semiconductor", Supplier Part Number 1=BC847CLT1GOSCT-ND, Value1="0.1 A", Value2=800
R1 R2 R4 R5 R6 R7 R8 R39 R40 R41 R42 R43 R44 R46 R47 R50 R51 R52 R53 R54 R55 R56 R57 R92 R93 R94 R95 R96 R97 R99 R100 R103 R104 R105 R106 R107 R108 R109 R110 R145 R146 R147 R148 R149 R150 R152 R153 R156 R157 R158 R159 R160 R161 R162 R163 R198 R199 R200 R201 R202 R203 R205 R206 R209 R210 R211 R212 R213 R214 R215 R216 R221 R222 R232 R233 R243 R244 R251 R252 R261 R263 R285 R286 R287 R288 R300 R301 R302 R303 R304 R305 R314 R317 R320 R322 R350 R351 R352 R353 R354 R355 R356 R362 R363 R364 R384 R392: library part CMP-0081856-1, "RES, 0, 0%, 0.2 W, AEC-Q200 Grade 0, 0402", Manufacturer=Vishay-Dale, Power_W=200mW, Supplier Part Number 1=541-0.0YBTR-ND, Tolerance_%=0%, Value2=0.2W, Value_Code=0
R3 R9 R45 R62: library part CMP-0026822-1, "RES, 0, 5%, 0.063 W, 0402", Manufacturer=Vishay-Dale, Power_W=63mW, Supplier Part Number 1=541-0.0JCT-ND, TempCo="200 ppm/C", Tolerance_%=5%, Value2=0.063W, Value_Code=0000, ValueDisplayed=0
R10 R12 R63 R65 R116 R118 R169 R171: library part CMP-0025958-3, "RES, 10.0 k, 1%, 0.063 W, AEC-Q200 Grade 0, 0402", Manufacturer=Vishay-Dale, Power_W=63mW, Supplier Part Number 1=541-10.0KLCT-ND, TempCo="100 ppm/C", Tolerance_%=1%, Value2=0.063W, Value_Code=10k0, ValueDisplayed=10.0k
